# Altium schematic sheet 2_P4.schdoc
size 307 x 218 mm; Name: VisionGuard; Symbol: Drawing-Symbol_A4; Device: Drawing-Symbol_A4; @Project Name: VisionGuard; @Page Count: 2; @Update Date: 2025-07-23; @Create Date: 2025-07-20; @Schematic Name: eye-protect_3; @Page No: 2; @Page Name: P4; Company: NXU; Version: V1.0; Page Size: A4; Drawn: Soha Saleh; @Create Time: 03:15:52; @Update Time: 05:29:28; Width: 1170; Height: 825; Region Start: 1; X Region Count: 6; Y Region Count: 4; Blade Width: 10; Title Block Position: 3; @Board Name: eye-protect_3
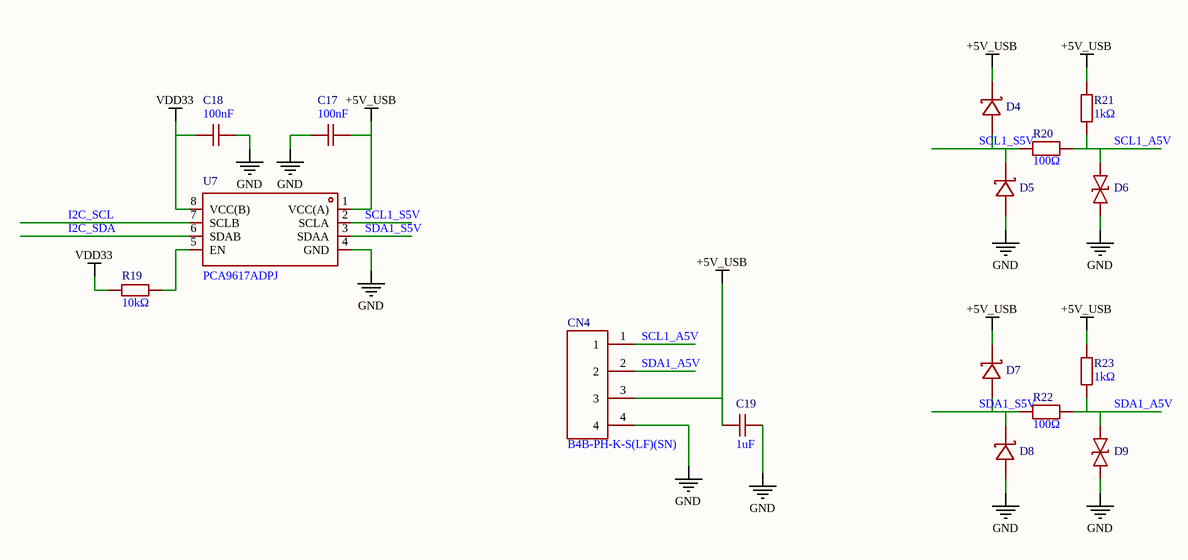
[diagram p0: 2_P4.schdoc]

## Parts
C17  100nF  [C0402]
C18  100nF  [C0402]
C19  1uF  [C0603]
CN4  B4B-PH-K-S(LF)(SN)  [CONN-TH_B4B-PH-K-S]
D4  CUS10S30,H3F  [SOD-323_L1.8-W1.3-LS2.5-RD]  (value not drawn)
D5  CUS10S30,H3F  [SOD-323_L1.8-W1.3-LS2.5-RD]  (value not drawn)
D6  ESD9B5.0ST5G  [SOD-923_L0.8-W0.6-LS1.0-BI]  (value not drawn)
D7  CUS10S30,H3F  [SOD-323_L1.8-W1.3-LS2.5-RD]  (value not drawn)
D8  CUS10S30,H3F  [SOD-323_L1.8-W1.3-LS2.5-RD]  (value not drawn)
D9  ESD9B5.0ST5G  [SOD-923_L0.8-W0.6-LS1.0-BI]  (value not drawn)
R19  10kΩ  [R0402]
R20  100Ω  [R0603]
R21  1kΩ  [R0402]
R22  100Ω  [R0603]
R23  1kΩ  [R0402]
U7  PCA9617ADPJ  [TSSOP-8_L3.0-W3.0-P0.65-LS4.9-BL]

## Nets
+5V_USB: C17.1 C19.1 CN4.3 D4.1(K) D7.1(K) R21.2 R23.2 U7.1(VCC(A))
GND: C17.2 C18.1 C19.2 CN4.4 D5.2(A) D6.2 D8.2(A) D9.2 U7.4(GND)
VDD33: C18.2 R19.1 U7.8(VCC(B))
I2C_SCL: U7.7(SCLB)
I2C_SDA: U7.6(SDAB)
SCL1_A5V: CN4.1 D6.1 R20.2 R21.1
SCL1_S5V: D4.2(A) D5.1(K) R20.1 U7.2(SCLA)
SDA1_A5V: CN4.2 D9.1 R22.2 R23.1
SDA1_S5V: D7.2(A) D8.1(K) R22.1 U7.3(SDAA)
NetR19_2: R19.2 U7.5(EN)

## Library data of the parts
C17 C18 = CL05B104KA5NNNC: Manufacturer: SAMSUNG(三星); Add into BOM: yes; Tolerance: ±10%
C19 = CL10B105KA8NNNC: Manufacturer: SAMSUNG(三星); Add into BOM: yes; Tolerance: ±10%
CN4 = B4B-PH-K-S(LF)(SN)_C131334: Manufacturer: JST; Add into BOM: yes; Pins Structure: 1x4P; Pitch: 2mm; Reference Series: PH; Number of PINs Per Row: 4; Current Rating (Max): 2A; Rated Voltage (Max): 100V; Plastic Material: PA66; Flame Retardant Rating: UL94V-0; Supplementary Features: K-leg punch; Z-Height of the Board: 6mm; X-Length of Bottom Edge on Board (Spacing Line): 9.9mm; Y-Width of Bottom Edge on Board: 4.5mm
D4 D5 D7 D8 = CUS10S30,H3F: Manufacturer: TOSHIBA(东芝); Add into BOM: yes; Forward Voltage (Vf@If): 230mV@100mA; Reverse Voltage (Vr): 30V; Average Rectified Current (Io): 1A; Reverse Leakage Current (Ir): 500uA@30V
D6 D9 = ESD9B5.0ST5G: Manufacturer: onsemi(安森美); Add into BOM: yes; polarity: Bi-Directional; Reverse Stand-Off Voltage (Vrwm): 5V; Breakdown Voltage: 5.8V; Number of Lines: 单路; Type: ESD
R19 = AC0402FR-0710KL: Manufacturer: YAGEO(国巨); Add into BOM: yes; Tolerance: ±1%; Temperature Coefficient: ±100ppm/℃
R20 R22 = ERJPA3J101V: Manufacturer: PANASONIC(松下); Add into BOM: yes; Tolerance: ±5%; Temperature Coefficient: ±200ppm/℃
R21 R23 = ERJ2RKF1001X_C242161: Manufacturer: PANASONIC(松下); Add into BOM: yes; Tolerance: ±1%; Temperature Coefficient: ±100ppm/℃
U7 = PCA9617ADPJ: Manufacturer: NXP(恩智浦); Add into BOM: yes; Input Type: 2-WireBus; Supply Voltage: 2.7V~5.5V; Number of Channels: 1; Input Capacitance: 10pF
